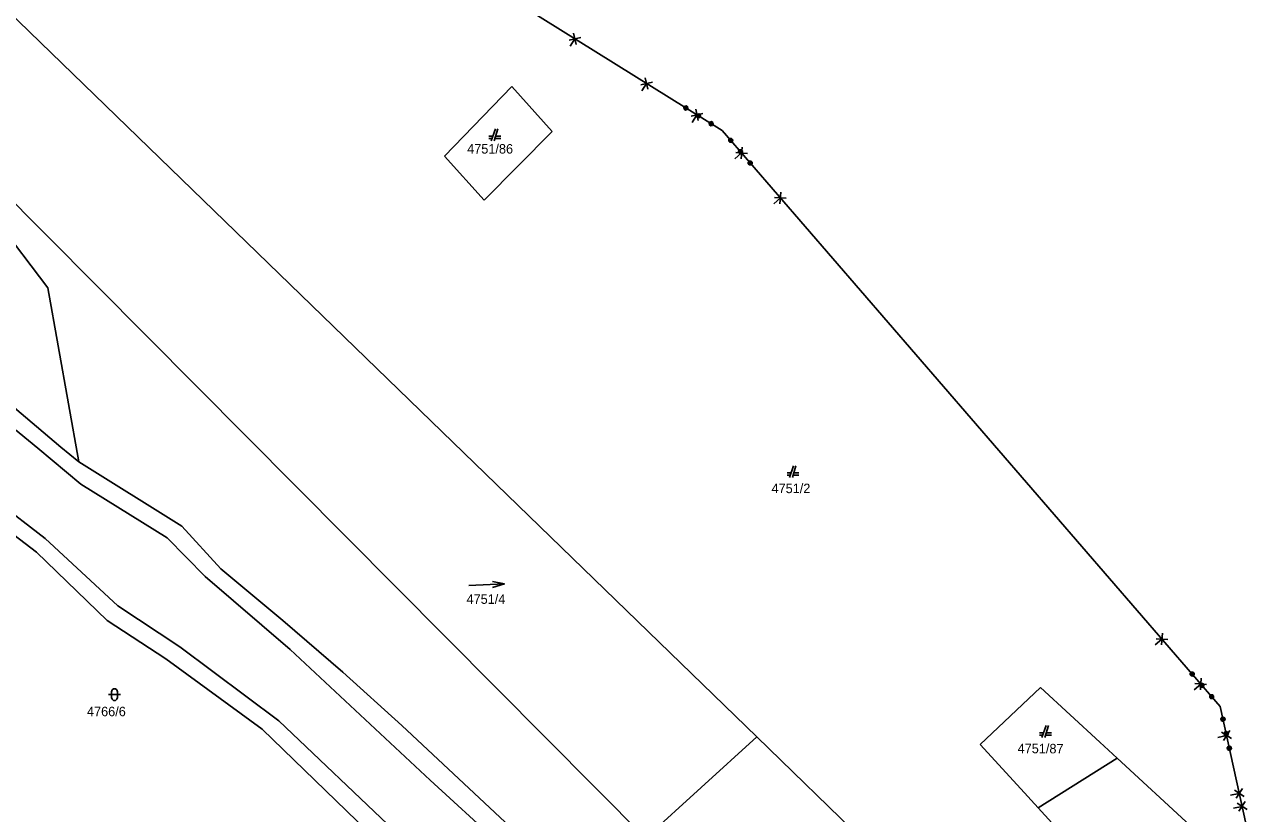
# Model space of a CAD drawing. Extents: x -266179 to -264727, y -1243225 to -1241702.
# Drawn here: x -265230.4 to -265022.1, y -1242141.6 to -1242008.7 of the extents above; entities that cross this region are included whole.
import ezdxf

# ---------------------------------------------------------------- set-up
doc = ezdxf.new("R2010")
doc.units = 0
for name, color, linetype in [('Vrstva 1', 7, 'Continuous'), ('Vrstva 19', 7, 'Continuous'), ('Vrstva 2', 7, 'Continuous'), ('Vrstva 21', 7, 'Continuous')]:
    doc.layers.add(name, color=color, linetype=linetype)

msp = doc.modelspace()

# ---------------------------------------------------------------- linework, layer by layer
at = {"layer": 'Vrstva 1'}
for p, q in [((-265299.18, -1241942.46), (-265107.1, -1242128.74)), ((-265125.85, -1242145.82), (-265309.66, -1241960.74)), ((-265150.47, -1242003.13), (-265112.94, -1242026.54)), ((-265159.72, -1242030.88), (-265148.39, -1242019.09)), ((-265148.39, -1242019.09), (-265141.57, -1242026.68)), ((-265141.57, -1242026.68), (-265153.01, -1242038.26)), ((-265151.13, -1242026.26), (-265151.83, -1242028.26)), ((-265151.33, -1242028.26), (-265150.73, -1242026.26)), ((-265112.94, -1242026.54), (-265029.05, -1242123.6)), ((-265151.55, -1242027.46), (-265152.23, -1242027.46)), ((-265152.23, -1242027.86), (-265151.69, -1242027.86)), ((-265151.21, -1242027.86), (-265150.23, -1242027.86)), ((-265150.23, -1242027.46), (-265151.09, -1242027.46)), ((-265242.79, -1242031.59), (-265226.55, -1242053.07)), ((-265153.01, -1242038.26), (-265159.72, -1242030.88)), ((-265226.55, -1242053.07), (-265221.33, -1242082.36)), ((-265224.35, -1242079.9), (-265251.43, -1242056.99)), ((-265260.34, -1242073.33), (-265228.42, -1242097.62)), ((-265221.33, -1242082.36), (-265224.35, -1242079.9)), ((-265203.96, -1242093.19), (-265221.33, -1242082.36)), ((-265100.92, -1242083.03), (-265101.62, -1242085.03)), ((-265101.12, -1242085.03), (-265100.52, -1242083.03)), ((-265101.34, -1242084.23), (-265102.02, -1242084.23)), ((-265102.02, -1242084.63), (-265101.48, -1242084.63)), ((-265101, -1242084.63), (-265100.02, -1242084.63)), ((-265100.02, -1242084.23), (-265100.88, -1242084.23)), ((-265197.4, -1242100.41), (-265203.96, -1242093.19)), ((-265228.42, -1242097.62), (-265216.54, -1242109.11)), ((-265186.93, -1242109.11), (-265197.4, -1242100.41)), ((-265155.627, -1242103.199), (-265149.633, -1242102.941)), ((-265216.54, -1242109.11), (-265206.68, -1242115.56)), ((-265176.83, -1242117.8), (-265186.93, -1242109.11)), ((-265206.68, -1242115.56), (-265190.45, -1242127.42)), ((-265166.93, -1242126.79), (-265176.83, -1242117.8)), ((-265069.51, -1242129.99), (-265059.31, -1242120.41)), ((-265059.31, -1242120.41), (-265049.31, -1242129.64)), ((-265029.05, -1242123.6), (-265022.13, -1242155.09)), ((-265145.62, -1242146.69), (-265166.93, -1242126.79)), ((-265058.38, -1242126.83), (-265059.08, -1242128.83)), ((-265058.58, -1242128.83), (-265057.98, -1242126.83)), ((-265190.45, -1242127.42), (-265169.7, -1242147.46)), ((-265125.85, -1242145.82), (-265107.1, -1242128.74)), ((-265107.1, -1242128.74), (-265077.56, -1242157.4)), ((-265058.8, -1242128.03), (-265059.48, -1242128.03)), ((-265059.48, -1242128.43), (-265058.94, -1242128.43)), ((-265058.46, -1242128.43), (-265057.48, -1242128.43)), ((-265057.48, -1242128.03), (-265058.34, -1242128.03)), ((-265062.62, -1242137.5), (-265069.51, -1242129.99)), ((-265049.31, -1242129.64), (-265046.38, -1242132.34)), ((-265059.7, -1242140.69), (-265046.38, -1242132.34)), ((-265046.38, -1242132.34), (-265059.7, -1242140.69)), ((-265046.38, -1242132.34), (-265034.09, -1242143.69)), ((-265059.7, -1242140.69), (-265062.62, -1242137.5)), ((-265048.64, -1242152.77), (-265059.7, -1242140.69))]:
    msp.add_line(p, q, dxfattribs=at)
for points in [[(-265151.652, -1242102.527), (-265149.633, -1242102.941), (-265151.609, -1242103.527)], [(-265216.32, -1242121.61), (-265215.05, -1242121.61), (-265214.32, -1242121.61)]]:
    msp.add_lwpolyline(points, dxfattribs=at)
msp.add_lwpolyline([(-265215.82, -1242121.11), (-265215.72, -1242120.82), (-265215.47, -1242120.64), (-265215.16, -1242120.64), (-265214.91, -1242120.82), (-265214.81, -1242121.11), (-265214.81, -1242122.11), (-265214.91, -1242122.4), (-265215.16, -1242122.58), (-265215.47, -1242122.58), (-265215.72, -1242122.4), (-265215.82, -1242122.11)], close=True, dxfattribs=at)
at = {"layer": 'Vrstva 19'}
for p, q in [((-265150.47, -1242003.13), (-265112.94, -1242026.54)), ((-265112.94, -1242026.54), (-265029.05, -1242123.6)), ((-265029.05, -1242123.6), (-265022.13, -1242155.09))]:
    msp.add_line(p, q, dxfattribs=at)
for points in [[(-265118.769, -1242022.526), (-265118.708, -1242022.788), (-265118.851, -1242023.017), (-265119.113, -1242023.077), (-265119.342, -1242022.934), (-265119.402, -1242022.672), (-265119.259, -1242022.443), (-265118.998, -1242022.383), (-265118.769, -1242022.526), (-265118.781, -1242022.565), (-265118.985, -1242022.438), (-265119.095, -1242022.463), (-265118.756, -1242022.675), (-265118.747, -1242022.775), (-265119.205, -1242022.489), (-265119.248, -1242022.557), (-265118.798, -1242022.837), (-265118.832, -1242022.911), (-265119.282, -1242022.63), (-265119.324, -1242022.698), (-265118.874, -1242022.979), (-265118.959, -1242023.02), (-265119.324, -1242022.792), (-265119.307, -1242022.897), (-265119.069, -1242023.045)], [(-265116.64, -1242023.855), (-265116.579, -1242024.117), (-265116.722, -1242024.346), (-265116.984, -1242024.407), (-265117.213, -1242024.264), (-265117.273, -1242024.002), (-265117.13, -1242023.773), (-265116.869, -1242023.712), (-265116.64, -1242023.855), (-265116.669, -1242023.884), (-265116.873, -1242023.757), (-265116.983, -1242023.782), (-265116.644, -1242023.994), (-265116.618, -1242024.104), (-265117.093, -1242023.808), (-265117.136, -1242023.876), (-265116.661, -1242024.172), (-265116.703, -1242024.24), (-265117.178, -1242023.943), (-265117.22, -1242024.011), (-265116.745, -1242024.308), (-265116.856, -1242024.333), (-265117.195, -1242024.122), (-265117.169, -1242024.232), (-265116.966, -1242024.359)], [(-265114.511, -1242025.185), (-265114.45, -1242025.446), (-265114.593, -1242025.675), (-265114.855, -1242025.736), (-265115.084, -1242025.593), (-265115.144, -1242025.331), (-265115.001, -1242025.102), (-265114.74, -1242025.042), (-265114.511, -1242025.185), (-265114.566, -1242025.197), (-265114.769, -1242025.07), (-265114.862, -1242025.106), (-265114.54, -1242025.308), (-265114.515, -1242025.418), (-265114.956, -1242025.142), (-265114.998, -1242025.21), (-265114.557, -1242025.486), (-265114.599, -1242025.554), (-265115.04, -1242025.278), (-265115.091, -1242025.341), (-265114.65, -1242025.616), (-265114.727, -1242025.663), (-265115.074, -1242025.446), (-265115.074, -1242025.54), (-265114.871, -1242025.667)], [(-265111.174, -1242028.093), (-265111.194, -1242028.361), (-265111.398, -1242028.538), (-265111.666, -1242028.518), (-265111.842, -1242028.314), (-265111.823, -1242028.046), (-265111.619, -1242027.87), (-265111.351, -1242027.889), (-265111.174, -1242028.093), (-265111.198, -1242028.127), (-265111.355, -1242027.946), (-265111.467, -1242027.937), (-265111.206, -1242028.24), (-265111.227, -1242028.338), (-265111.58, -1242027.929), (-265111.641, -1242027.981), (-265111.294, -1242028.382), (-265111.348, -1242028.442), (-265111.695, -1242028.041), (-265111.755, -1242028.094), (-265111.409, -1242028.495), (-265111.502, -1242028.509), (-265111.783, -1242028.184), (-265111.798, -1242028.289), (-265111.615, -1242028.501)], [(-265109.533, -1242029.993), (-265109.552, -1242030.261), (-265109.757, -1242030.437), (-265110.025, -1242030.418), (-265110.201, -1242030.213), (-265110.182, -1242029.945), (-265109.977, -1242029.769), (-265109.709, -1242029.788), (-265109.533, -1242029.993), (-265109.57, -1242030.011), (-265109.727, -1242029.83), (-265109.84, -1242029.821), (-265109.578, -1242030.124), (-265109.586, -1242030.237), (-265109.952, -1242029.813), (-265110.013, -1242029.865), (-265109.647, -1242030.289), (-265109.707, -1242030.341), (-265110.073, -1242029.918), (-265110.134, -1242029.97), (-265109.768, -1242030.394), (-265109.881, -1242030.386), (-265110.142, -1242030.083), (-265110.15, -1242030.196), (-265109.993, -1242030.377)], [(-265107.892, -1242031.892), (-265107.911, -1242032.16), (-265108.116, -1242032.336), (-265108.384, -1242032.317), (-265108.56, -1242032.112), (-265108.541, -1242031.844), (-265108.336, -1242031.668), (-265108.068, -1242031.688), (-265107.892, -1242031.892), (-265107.948, -1242031.888), (-265108.105, -1242031.706), (-265108.205, -1242031.713), (-265107.957, -1242032.001), (-265107.965, -1242032.113), (-265108.305, -1242031.72), (-265108.365, -1242031.772), (-265108.025, -1242032.166), (-265108.086, -1242032.218), (-265108.426, -1242031.825), (-265108.493, -1242031.869), (-265108.153, -1242032.263), (-265108.24, -1242032.285), (-265108.508, -1242031.975), (-265108.535, -1242032.065), (-265108.379, -1242032.246)], [(-265033.431, -1242118.042), (-265033.45, -1242118.31), (-265033.655, -1242118.486), (-265033.923, -1242118.467), (-265034.099, -1242118.262), (-265034.08, -1242117.994), (-265033.875, -1242117.818), (-265033.607, -1242117.837), (-265033.431, -1242118.042), (-265033.455, -1242118.075), (-265033.611, -1242117.894), (-265033.724, -1242117.886), (-265033.463, -1242118.188), (-265033.484, -1242118.286), (-265033.837, -1242117.877), (-265033.898, -1242117.93), (-265033.551, -1242118.331), (-265033.605, -1242118.39), (-265033.952, -1242117.989), (-265034.012, -1242118.042), (-265033.666, -1242118.443), (-265033.759, -1242118.457), (-265034.04, -1242118.132), (-265034.055, -1242118.237), (-265033.872, -1242118.449)], [(-265031.79, -1242119.941), (-265031.809, -1242120.209), (-265032.014, -1242120.385), (-265032.282, -1242120.366), (-265032.458, -1242120.162), (-265032.439, -1242119.894), (-265032.234, -1242119.717), (-265031.966, -1242119.737), (-265031.79, -1242119.941), (-265031.827, -1242119.959), (-265031.983, -1242119.778), (-265032.096, -1242119.77), (-265031.835, -1242120.072), (-265031.843, -1242120.185), (-265032.209, -1242119.761), (-265032.27, -1242119.814), (-265031.904, -1242120.237), (-265031.964, -1242120.29), (-265032.33, -1242119.866), (-265032.391, -1242119.918), (-265032.025, -1242120.342), (-265032.137, -1242120.334), (-265032.399, -1242120.031), (-265032.407, -1242120.144), (-265032.25, -1242120.326)], [(-265030.149, -1242121.84), (-265030.168, -1242122.108), (-265030.372, -1242122.285), (-265030.64, -1242122.265), (-265030.817, -1242122.061), (-265030.797, -1242121.793), (-265030.593, -1242121.616), (-265030.325, -1242121.636), (-265030.149, -1242121.84), (-265030.205, -1242121.836), (-265030.362, -1242121.654), (-265030.462, -1242121.661), (-265030.213, -1242121.949), (-265030.222, -1242122.062), (-265030.562, -1242121.668), (-265030.622, -1242121.72), (-265030.282, -1242122.114), (-265030.343, -1242122.166), (-265030.683, -1242121.773), (-265030.75, -1242121.817), (-265030.41, -1242122.211), (-265030.496, -1242122.233), (-265030.764, -1242121.923), (-265030.792, -1242122.013), (-265030.635, -1242122.194)], [(-265028.238, -1242125.807), (-265028.383, -1242126.033), (-265028.646, -1242126.091), (-265028.873, -1242125.947), (-265028.931, -1242125.683), (-265028.786, -1242125.457), (-265028.522, -1242125.399), (-265028.296, -1242125.543), (-265028.238, -1242125.807), (-265028.275, -1242125.825), (-265028.327, -1242125.591), (-265028.422, -1242125.53), (-265028.336, -1242125.921), (-265028.401, -1242125.997), (-265028.517, -1242125.469), (-265028.595, -1242125.486), (-265028.481, -1242126.004), (-265028.557, -1242126.031), (-265028.671, -1242125.513), (-265028.749, -1242125.531), (-265028.636, -1242126.048), (-265028.724, -1242126.016), (-265028.817, -1242125.597), (-265028.88, -1242125.682), (-265028.82, -1242125.956)], [(-265027.699, -1242128.258), (-265027.843, -1242128.485), (-265028.107, -1242128.543), (-265028.333, -1242128.398), (-265028.391, -1242128.134), (-265028.247, -1242127.908), (-265027.983, -1242127.85), (-265027.757, -1242127.995), (-265027.699, -1242128.258), (-265027.74, -1242128.257), (-265027.791, -1242128.023), (-265027.887, -1242127.962), (-265027.801, -1242128.353), (-265027.862, -1242128.448), (-265027.982, -1242127.901), (-265028.06, -1242127.918), (-265027.94, -1242128.465), (-265028.018, -1242128.482), (-265028.138, -1242127.935), (-265028.216, -1242127.953), (-265028.096, -1242128.499), (-265028.191, -1242128.439), (-265028.277, -1242128.048), (-265028.338, -1242128.143), (-265028.287, -1242128.378)], [(-265027.159, -1242130.71), (-265027.304, -1242130.936), (-265027.568, -1242130.994), (-265027.794, -1242130.849), (-265027.852, -1242130.586), (-265027.707, -1242130.359), (-265027.444, -1242130.301), (-265027.217, -1242130.446), (-265027.159, -1242130.71), (-265027.207, -1242130.679), (-265027.258, -1242130.445), (-265027.349, -1242130.404), (-265027.268, -1242130.775), (-265027.329, -1242130.87), (-265027.44, -1242130.362), (-265027.519, -1242130.379), (-265027.407, -1242130.887), (-265027.485, -1242130.904), (-265027.597, -1242130.396), (-265027.677, -1242130.404), (-265027.565, -1242130.912), (-265027.652, -1242130.89), (-265027.74, -1242130.489), (-265027.807, -1242130.555), (-265027.756, -1242130.79)]]:
    msp.add_lwpolyline(points, dxfattribs=at)
at = {"layer": 'Vrstva 2'}
for p, q in [((-265252.36, -1242060.2), (-265228.25, -1242080.06)), ((-265227.01, -1242095.32), (-265260.16, -1242069.72)), ((-265228.25, -1242080.06), (-265220.98, -1242086.13)), ((-265220.98, -1242086.13), (-265206.44, -1242095.16)), ((-265214.77, -1242106.65), (-265227.01, -1242095.32)), ((-265206.44, -1242095.16), (-265200.05, -1242101.72)), ((-265200.05, -1242101.72), (-265185.69, -1242114.03)), ((-265204.31, -1242113.54), (-265214.77, -1242106.65)), ((-265187.64, -1242126.01), (-265204.31, -1242113.54)), ((-265185.69, -1242114.03), (-265162.11, -1242136.02)), ((-265168.14, -1242144.55), (-265187.64, -1242126.01)), ((-265162.11, -1242136.02), (-265147.75, -1242149.15))]:
    msp.add_line(p, q, dxfattribs=at)
at = {"layer": 'Vrstva 21'}
for p, q in [((-265150.47, -1242003.13), (-265112.94, -1242026.54)), ((-265137.967, -1242010.106), (-265137.521, -1242012.035)), ((-265136.78, -1242010.848), (-265138.709, -1242011.294)), ((-265137.744, -1242011.071), (-265138.539, -1242012.343)), ((-265124.701, -1242018.376), (-265126.63, -1242018.822)), ((-265125.666, -1242018.599), (-265126.46, -1242019.872)), ((-265125.889, -1242017.635), (-265125.443, -1242019.564)), ((-265117.407, -1242022.931), (-265116.961, -1242024.86)), ((-265116.219, -1242023.673), (-265118.148, -1242024.119)), ((-265117.184, -1242023.896), (-265117.978, -1242025.168)), ((-265112.94, -1242026.54), (-265029.05, -1242123.6)), ((-265109.598, -1242029.335), (-265109.742, -1242031.31)), ((-265109.67, -1242030.322), (-265110.805, -1242031.303)), ((-265108.683, -1242030.394), (-265110.657, -1242030.25)), ((-265102.144, -1242037.961), (-265104.119, -1242037.817)), ((-265103.06, -1242036.902), (-265103.204, -1242038.876)), ((-265103.132, -1242037.889), (-265104.267, -1242038.87)), ((-265038.858, -1242112.251), (-265039.993, -1242113.232)), ((-265037.871, -1242112.323), (-265039.846, -1242112.179)), ((-265038.786, -1242111.264), (-265038.93, -1242113.238)), ((-265032.248, -1242118.83), (-265032.392, -1242120.805)), ((-265032.32, -1242119.818), (-265033.455, -1242120.798)), ((-265031.333, -1242119.89), (-265033.307, -1242119.746)), ((-265029.05, -1242123.6), (-265022.13, -1242155.09)), ((-265027.978, -1242128.484), (-265029.443, -1242128.806)), ((-265027.144, -1242129.017), (-265028.812, -1242127.951)), ((-265027.445, -1242127.65), (-265028.511, -1242129.318)), ((-265024.995, -1242138.783), (-265026.663, -1242137.717)), ((-265025.296, -1242137.416), (-265026.362, -1242139.084)), ((-265025.829, -1242138.25), (-265027.294, -1242138.572)), ((-265024.517, -1242140.973), (-265026.185, -1242139.907)), ((-265024.818, -1242139.606), (-265025.884, -1242141.274)), ((-265025.351, -1242140.44), (-265026.816, -1242140.762))]:
    msp.add_line(p, q, dxfattribs=at)

# ---------------------------------------------------------------- texts
at = {"layer": 'Vrstva 1'}
for s, p in [('4751/86', (-265155.902, -1242030.42)), ('4751/2', (-265104.63, -1242087.65)), ('4751/4', (-265156.01, -1242106.31)), ('4766/6', (-265219.945, -1242125.25))]:
    msp.add_text(s, height=1.6, dxfattribs=at).set_placement(p)
msp.add_text('4751/87', height=1.6, rotation=359.7029, dxfattribs=at).set_placement((-265063.176, -1242131.477))

doc.saveas('drawing.dxf')
